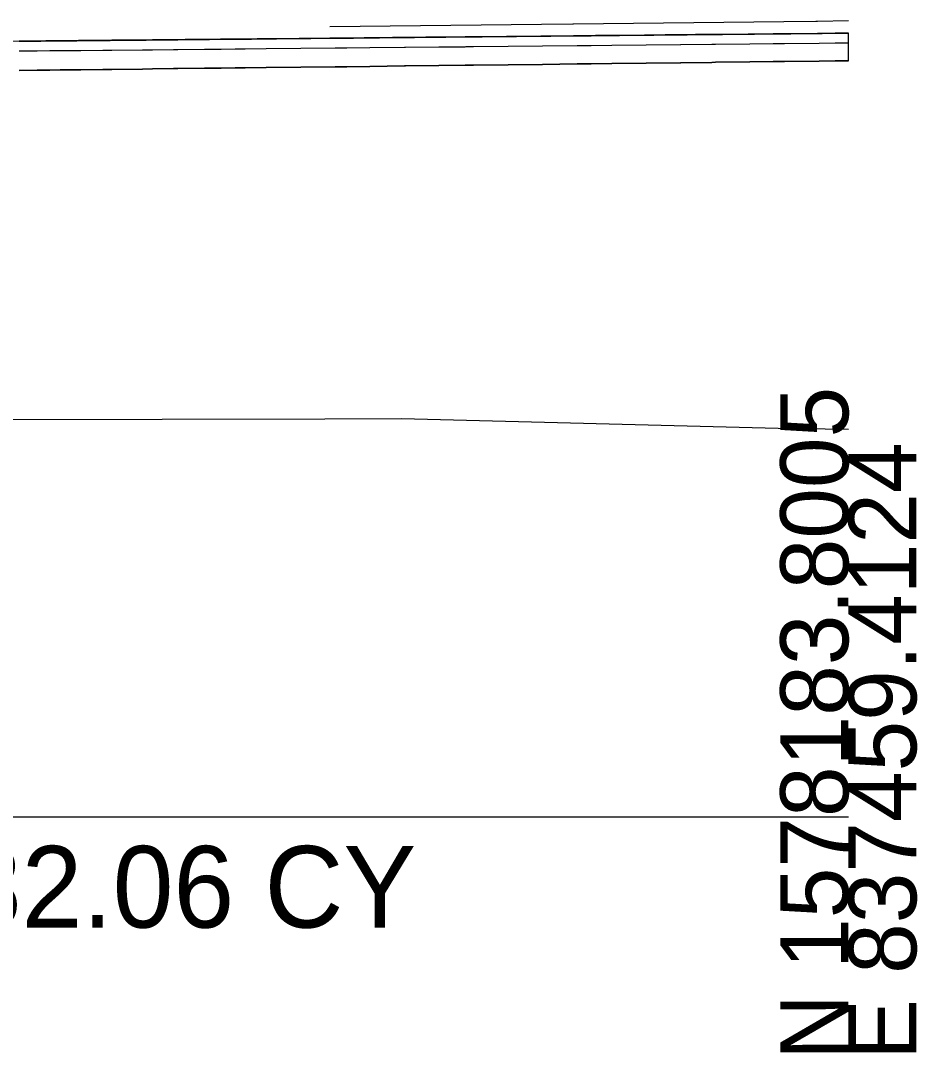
# Model space of a CAD drawing. Extents: x -26 to 303, y -16 to 6048.
# Drawn here: x 265.95 to 302.84, y 5990.31 to 6032.76 of the extents above; entities that cross this region are included whole.
import ezdxf

# ---------------------------------------------------------------- set-up
doc = ezdxf.new("R2010")
doc.units = 0
for name, color, linetype in [('CONST_LV3', 7, 'Continuous'), ('DTM_P_FINISHED_GRADE2', 7, 'Continuous'), ('DTM_X_GROUND', 7, 'Continuous'), ('XS_CELL', 7, 'Continuous'), ('XS_M_SHAPES_EARTHWORK', 7, 'Continuous'), ('XS_P_ASPHALT', 7, 'Continuous'), ('XS_P_SHOULDER', 7, 'Continuous'), ('XS_P_SUBGRADE_GRANULAR', 7, 'Continuous'), ('XS_SHEET_EW_TX_VOLUME', 7, 'Continuous')]:
    doc.layers.add(name, color=color, linetype=linetype)

msp = doc.modelspace()

# ---------------------------------------------------------------- linework, layer by layer
at = {"layer": 'CONST_LV3'}
for points in [[(278.666, 6032.514), (287.381, 6032.613), (288.666, 6032.627), (288.697, 6032.628), (297.343, 6032.728), (298.667, 6032.744), (298.728, 6032.744), (300, 6032.759)], [(278.666, 6032.514), (287.381, 6032.613), (288.666, 6032.627), (288.697, 6032.628), (297.343, 6032.728), (298.667, 6032.744), (298.728, 6032.744), (300, 6032.759)], [(300, 6032.247), (298.729, 6032.234), (297.181, 6032.218), (296.244, 6032.209), (294.294, 6032.189), (293.713, 6032.183), (292.532, 6032.171), (292.463, 6032.17), (292.173, 6032.167), (288.744, 6032.133), (288.719, 6032.133), (288.698, 6032.133), (286.047, 6032.106), (283.682, 6032.083), (282.621, 6032.073), (281.244, 6032.059), (280.081, 6032.048), (278.666, 6032.034), (278.122, 6032.029), (277.485, 6032.023), (275.68, 6032.005), (273.744, 6031.987), (273.698, 6031.986), (273.65, 6031.986), (273.22, 6031.982), (272.777, 6031.978), (270.627, 6031.957), (268.634, 6031.939), (266.2, 6031.916), (264.364, 6031.899)]]:
    msp.add_lwpolyline(points, dxfattribs=at)
at = {"layer": 'DTM_P_FINISHED_GRADE2'}
msp.add_lwpolyline([(265.884, 6031.913), (266.206, 6031.916), (266.629, 6031.92), (266.933, 6031.923), (267.154, 6031.925), (267.399, 6031.927), (267.571, 6031.929), (267.917, 6031.932), (268.425, 6031.937), (268.973, 6031.942), (269.323, 6031.945), (269.465, 6031.947), (269.695, 6031.949), (270.5, 6031.956), (270.965, 6031.961), (271.112, 6031.962), (271.376, 6031.964), (271.94, 6031.97), (272.235, 6031.973), (272.295, 6031.973), (272.412, 6031.974), (272.774, 6031.978), (273.505, 6031.985), (273.721, 6031.987), (274.168, 6031.991), (274.179, 6031.991), (274.202, 6031.991), (274.386, 6031.993), (274.775, 6031.997), (274.904, 6031.998), (275.181, 6032.001), (275.451, 6032.003), (276.045, 6032.009), (276.479, 6032.013), (277.468, 6032.023), (277.888, 6032.027), (278.89, 6032.036), (278.918, 6032.037), (278.972, 6032.037), (279.04, 6032.038), (279.096, 6032.038), (279.229, 6032.04), (279.368, 6032.041), (279.638, 6032.044), (280.312, 6032.05), (280.707, 6032.054), (281.734, 6032.064), (281.745, 6032.064), (281.775, 6032.064), (282.146, 6032.068), (283.156, 6032.078), (283.439, 6032.081), (284.235, 6032.088), (284.246, 6032.089), (284.324, 6032.089), (284.354, 6032.09), (284.578, 6032.092), (284.938, 6032.095), (286, 6032.106), (286.348, 6032.109), (287.422, 6032.12), (287.759, 6032.123), (288.844, 6032.134), (288.96, 6032.135), (289.345, 6032.139), (289.361, 6032.139), (289.414, 6032.14), (289.608, 6032.142), (290.266, 6032.148), (290.582, 6032.151), (291.688, 6032.163), (291.991, 6032.166), (293.098, 6032.177), (293.101, 6032.177), (293.109, 6032.177), (293.374, 6032.18), (294.38, 6032.19), (294.411, 6032.19), (294.531, 6032.191), (294.816, 6032.194), (295.953, 6032.206), (296.14, 6032.208), (296.914, 6032.216), (297.002, 6032.216), (297.374, 6032.22), (297.64, 6032.223), (298.796, 6032.235), (298.917, 6032.236), (299.459, 6032.242), (299.595, 6032.243), (300, 6032.247)], dxfattribs=at)
at = {"layer": 'DTM_X_GROUND'}
for points in [[(265.884, 6031.913), (266.308, 6031.917), (266.629, 6031.92), (266.78, 6031.921), (266.985, 6031.923), (267.084, 6031.924), (267.154, 6031.925), (267.327, 6031.927), (267.571, 6031.929), (267.849, 6031.931), (268.256, 6031.935), (268.323, 6031.936), (268.425, 6031.937), (268.973, 6031.942), (269.323, 6031.945), (269.448, 6031.946), (269.526, 6031.947), (269.631, 6031.948), (269.695, 6031.949), (270.105, 6031.953), (270.796, 6031.959), (270.904, 6031.96), (270.965, 6031.961), (271.112, 6031.962), (271.376, 6031.964), (271.828, 6031.969), (272.066, 6031.971), (272.178, 6031.972), (272.235, 6031.973), (272.295, 6031.973), (272.412, 6031.974), (272.719, 6031.977), (273.336, 6031.983), (273.392, 6031.984), (273.505, 6031.985), (273.721, 6031.987), (274.168, 6031.991), (274.179, 6031.991), (274.309, 6031.992), (274.333, 6031.993), (274.607, 6031.995), (274.661, 6031.996), (274.775, 6031.997), (274.904, 6031.998), (275.181, 6032.001), (275.399, 6032.003), (275.876, 6032.007), (275.892, 6032.007), (275.908, 6032.008), (275.929, 6032.008), (275.964, 6032.008), (275.999, 6032.008), (276.045, 6032.009), (276.458, 6032.013), (277.4, 6032.022), (277.42, 6032.022), (277.468, 6032.023), (277.868, 6032.026), (278.822, 6032.036), (278.842, 6032.036), (278.87, 6032.036), (278.924, 6032.037), (278.972, 6032.037), (279.04, 6032.038), (279.096, 6032.038), (279.229, 6032.04), (279.368, 6032.041), (279.619, 6032.043), (280.244, 6032.049), (280.264, 6032.05), (280.312, 6032.05), (280.689, 6032.054), (281.667, 6032.063), (281.685, 6032.063), (281.696, 6032.064), (281.745, 6032.064), (281.775, 6032.064), (282.128, 6032.068), (283.089, 6032.077), (283.107, 6032.077), (283.156, 6032.078), (283.439, 6032.081), (284.235, 6032.088), (284.246, 6032.089), (284.307, 6032.089), (284.336, 6032.089), (284.354, 6032.09), (284.528, 6032.091), (284.578, 6032.092), (284.921, 6032.095), (285.933, 6032.105), (285.95, 6032.105), (286, 6032.106), (286.332, 6032.109), (287.355, 6032.119), (287.371, 6032.119), (287.422, 6032.12), (287.743, 6032.123), (288.777, 6032.133), (288.792, 6032.134), (288.844, 6032.134), (288.96, 6032.135), (289.345, 6032.139), (289.361, 6032.139), (289.414, 6032.14), (289.593, 6032.142), (290.198, 6032.148), (290.214, 6032.148), (290.266, 6032.148), (290.567, 6032.151), (291.62, 6032.162), (291.635, 6032.162), (291.688, 6032.163), (291.979, 6032.165), (293.042, 6032.176), (293.054, 6032.176), (293.056, 6032.176), (293.101, 6032.177), (293.109, 6032.177), (293.374, 6032.18), (294.38, 6032.19), (294.397, 6032.19), (294.411, 6032.19), (294.477, 6032.191), (294.531, 6032.191), (294.803, 6032.194), (295.885, 6032.205), (295.898, 6032.205), (295.953, 6032.206), (296.14, 6032.208), (296.914, 6032.216), (296.989, 6032.216), (297.002, 6032.216), (297.319, 6032.22), (297.374, 6032.22), (297.628, 6032.223), (298.728, 6032.234), (298.74, 6032.234), (298.796, 6032.235), (298.917, 6032.236), (299.459, 6032.242), (299.583, 6032.243), (300, 6032.247)], [(221.804, 6016.289), (230.273, 6016.114), (237.507, 6016.127), (244.659, 6016.14), (251.731, 6016.152), (258.137, 6016.339), (264.993, 6016.353), (271.767, 6016.367), (278.46, 6016.381), (281.614, 6016.388), (297.107, 6015.991), (300, 6015.945)]]:
    msp.add_lwpolyline(points, dxfattribs=at)
at = {"layer": 'XS_CELL'}
msp.add_line((150, 6000), (300, 6000), dxfattribs=at)
at = {"layer": 'XS_M_SHAPES_EARTHWORK'}
msp.add_lwpolyline([(265.884, 6030.712), (266.629, 6030.721), (267.154, 6030.726), (267.571, 6030.731), (268.425, 6030.741), (269.323, 6030.751), (269.695, 6030.755), (270.965, 6030.769), (271.376, 6030.774), (272.235, 6030.784), (272.412, 6030.786), (273.505, 6030.798), (274.168, 6030.806), (274.202, 6030.806), (274.775, 6030.813), (275.181, 6030.817), (276.045, 6030.827), (277.468, 6030.844), (278.89, 6030.86), (278.985, 6030.861), (279.172, 6030.863), (279.368, 6030.865), (280.312, 6030.876), (281.734, 6030.893), (281.775, 6030.893), (283.156, 6030.909), (284.235, 6030.922), (284.275, 6030.923), (284.578, 6030.926), (286, 6030.943), (287.422, 6030.96), (288.844, 6030.976), (289.345, 6030.982), (289.414, 6030.983), (290.266, 6030.993), (291.688, 6031.01), (293.098, 6031.027), (293.109, 6031.027), (294.38, 6031.043), (294.531, 6031.044), (295.953, 6031.062), (296.914, 6031.073), (297.374, 6031.079), (298.796, 6031.096), (299.459, 6031.104), (300, 6031.111), (300, 6032.247), (299.583, 6032.243), (299.459, 6032.242), (298.917, 6032.236), (298.796, 6032.235), (298.74, 6032.234), (298.728, 6032.234), (297.628, 6032.223), (297.374, 6032.22), (297.319, 6032.22), (297.002, 6032.216), (296.989, 6032.216), (296.914, 6032.216), (296.14, 6032.208), (295.953, 6032.206), (295.898, 6032.205), (295.885, 6032.205), (294.803, 6032.194), (294.531, 6032.191), (294.477, 6032.191), (294.411, 6032.19), (294.397, 6032.19), (294.38, 6032.19), (293.374, 6032.18), (293.109, 6032.177), (293.101, 6032.177), (293.056, 6032.176), (293.054, 6032.176), (293.042, 6032.176), (291.979, 6032.165), (291.688, 6032.163), (291.635, 6032.162), (291.62, 6032.162), (290.567, 6032.151), (290.266, 6032.148), (290.214, 6032.148), (290.198, 6032.148), (289.593, 6032.142), (289.414, 6032.14), (289.361, 6032.139), (289.345, 6032.139), (288.96, 6032.135), (288.844, 6032.134), (288.792, 6032.134), (288.777, 6032.133), (287.743, 6032.123), (287.422, 6032.12), (287.371, 6032.119), (287.355, 6032.119), (286.332, 6032.109), (286, 6032.106), (285.95, 6032.105), (285.933, 6032.105), (284.921, 6032.095), (284.578, 6032.092), (284.528, 6032.091), (284.354, 6032.09), (284.336, 6032.089), (284.307, 6032.089), (284.246, 6032.089), (284.235, 6032.088), (283.439, 6032.081), (283.156, 6032.078), (283.107, 6032.077), (283.089, 6032.077), (282.128, 6032.068), (281.775, 6032.064), (281.745, 6032.064), (281.696, 6032.064), (281.685, 6032.063), (281.667, 6032.063), (280.689, 6032.054), (280.312, 6032.05), (280.264, 6032.05), (280.244, 6032.049), (279.619, 6032.043), (279.368, 6032.041), (279.229, 6032.04), (279.096, 6032.038), (279.04, 6032.038), (278.972, 6032.037), (278.924, 6032.037), (278.87, 6032.036), (278.842, 6032.036), (278.822, 6032.036), (277.868, 6032.026), (277.468, 6032.023), (277.42, 6032.022), (277.4, 6032.022), (276.458, 6032.013), (276.045, 6032.009), (275.999, 6032.008), (275.964, 6032.008), (275.929, 6032.008), (275.908, 6032.008), (275.892, 6032.007), (275.876, 6032.007), (275.399, 6032.003), (275.181, 6032.001), (274.904, 6031.998), (274.775, 6031.997), (274.661, 6031.996), (274.607, 6031.995), (274.333, 6031.993), (274.309, 6031.992), (274.179, 6031.991), (274.168, 6031.991), (273.721, 6031.987), (273.505, 6031.985), (273.392, 6031.984), (273.336, 6031.983), (272.719, 6031.977), (272.412, 6031.974), (272.295, 6031.973), (272.235, 6031.973), (272.178, 6031.972), (272.066, 6031.971), (271.828, 6031.969), (271.376, 6031.964), (271.112, 6031.962), (270.965, 6031.961), (270.904, 6031.96), (270.796, 6031.959), (270.105, 6031.953), (269.695, 6031.949), (269.631, 6031.948), (269.526, 6031.947), (269.448, 6031.946), (269.323, 6031.945), (268.973, 6031.942), (268.425, 6031.937), (268.323, 6031.936), (268.256, 6031.935), (267.849, 6031.931), (267.571, 6031.929), (267.327, 6031.927), (267.154, 6031.925), (267.084, 6031.924), (266.985, 6031.923), (266.78, 6031.921), (266.629, 6031.92), (266.308, 6031.917), (265.884, 6031.913)], dxfattribs=at)
at = {"layer": 'XS_P_ASPHALT'}
for points in [[(300, 6031.847), (300, 6032.247), (300, 6032.247), (299.459, 6032.242), (299.459, 6032.242), (298.796, 6032.235), (298.796, 6032.235), (297.374, 6032.22), (297.374, 6032.22), (296.914, 6032.216), (296.914, 6032.216), (295.953, 6032.206), (295.953, 6032.206), (294.531, 6032.191), (294.531, 6032.191), (294.38, 6032.19), (294.38, 6032.19), (293.109, 6032.177), (293.109, 6032.177), (293.098, 6032.177), (293.098, 6032.177), (291.688, 6032.163), (291.688, 6032.163), (290.266, 6032.148), (290.266, 6032.148), (289.414, 6032.14), (289.414, 6032.14), (289.345, 6032.139), (289.345, 6032.139), (288.844, 6032.134), (288.844, 6032.134), (287.422, 6032.12), (287.422, 6032.12), (286, 6032.106), (286, 6032.106), (284.578, 6032.092), (284.578, 6032.092), (284.275, 6032.089), (284.275, 6032.089), (284.235, 6032.088), (284.235, 6032.088), (283.156, 6032.078), (283.156, 6032.078), (281.775, 6032.064), (281.775, 6032.064), (281.734, 6032.064), (281.734, 6032.064), (280.312, 6032.05), (280.312, 6032.05), (279.368, 6032.041), (279.368, 6032.041), (279.172, 6032.039), (279.172, 6032.039), (278.985, 6032.037), (278.985, 6032.037), (278.89, 6032.036), (278.89, 6032.036), (277.468, 6032.023), (277.468, 6032.023), (276.045, 6032.009), (276.045, 6032.009), (275.181, 6032.001), (275.181, 6032.001), (274.775, 6031.997), (274.775, 6031.997), (274.202, 6031.991), (274.202, 6031.991), (274.168, 6031.991), (274.168, 6031.991), (273.505, 6031.985), (273.505, 6031.985), (272.412, 6031.974), (272.412, 6031.974), (272.235, 6031.973), (272.235, 6031.973), (271.376, 6031.964), (271.376, 6031.964), (270.965, 6031.961), (270.965, 6031.961), (269.695, 6031.949), (269.695, 6031.949), (269.323, 6031.945), (269.323, 6031.945), (268.425, 6031.937), (268.425, 6031.937), (267.571, 6031.929), (267.571, 6031.929), (267.154, 6031.925), (267.154, 6031.925), (266.629, 6031.92), (266.629, 6031.92), (265.884, 6031.913)], [(265.884, 6031.513), (266.629, 6031.52), (266.629, 6031.52), (267.154, 6031.525), (267.154, 6031.525), (267.571, 6031.529), (267.571, 6031.529), (268.425, 6031.537), (268.425, 6031.537), (269.323, 6031.545), (269.323, 6031.545), (269.695, 6031.549), (269.695, 6031.549), (270.965, 6031.561), (270.965, 6031.561), (271.376, 6031.564), (271.376, 6031.564), (272.235, 6031.573), (272.235, 6031.573), (272.412, 6031.574), (272.412, 6031.574), (273.505, 6031.585), (273.505, 6031.585), (274.168, 6031.591), (274.168, 6031.591), (274.202, 6031.591), (274.202, 6031.591), (274.775, 6031.597), (274.775, 6031.597), (275.181, 6031.601), (275.181, 6031.601), (276.045, 6031.609), (276.045, 6031.609), (277.468, 6031.623), (277.468, 6031.623), (278.89, 6031.636), (278.89, 6031.636), (278.985, 6031.637), (278.985, 6031.637), (279.172, 6031.639), (279.172, 6031.639), (279.368, 6031.641), (279.368, 6031.641), (280.312, 6031.65), (280.312, 6031.65), (281.734, 6031.664), (281.734, 6031.664), (281.775, 6031.664), (281.775, 6031.664), (283.156, 6031.678), (283.156, 6031.678), (284.235, 6031.688), (284.235, 6031.688), (284.275, 6031.689), (284.275, 6031.689), (284.578, 6031.692), (284.578, 6031.692), (286, 6031.706), (286, 6031.706), (287.422, 6031.72), (287.422, 6031.72), (288.844, 6031.734), (288.844, 6031.734), (289.345, 6031.739), (289.345, 6031.739), (289.414, 6031.74), (289.414, 6031.74), (290.266, 6031.748), (290.266, 6031.748), (291.688, 6031.763), (291.688, 6031.763), (293.098, 6031.777), (293.098, 6031.777), (293.109, 6031.777), (293.109, 6031.777), (294.38, 6031.79), (294.38, 6031.79), (294.531, 6031.791), (294.531, 6031.791), (295.953, 6031.806), (295.953, 6031.806), (296.914, 6031.816), (296.914, 6031.816), (297.374, 6031.82), (297.374, 6031.82), (298.796, 6031.835), (298.796, 6031.835), (299.459, 6031.842), (299.459, 6031.842), (300, 6031.847)]]:
    msp.add_lwpolyline(points, dxfattribs=at)
at = {"layer": 'XS_P_SHOULDER'}
msp.add_lwpolyline([(300, 6032.247), (299.459, 6032.242), (298.796, 6032.235), (297.374, 6032.22), (296.914, 6032.216), (295.953, 6032.206), (294.531, 6032.191), (294.38, 6032.19), (293.109, 6032.177), (293.098, 6032.177), (291.688, 6032.163), (290.266, 6032.148), (289.414, 6032.14), (289.345, 6032.139), (288.844, 6032.134), (287.422, 6032.12), (286, 6032.106), (284.578, 6032.092), (284.275, 6032.089), (284.235, 6032.088), (283.156, 6032.078), (281.775, 6032.064), (281.734, 6032.064), (280.312, 6032.05), (279.368, 6032.041), (279.172, 6032.039), (278.985, 6032.037), (278.89, 6032.036), (277.468, 6032.023), (276.045, 6032.009), (275.181, 6032.001), (274.775, 6031.997), (274.202, 6031.991), (274.168, 6031.991), (273.505, 6031.985), (272.412, 6031.974), (272.235, 6031.973), (271.376, 6031.964), (270.965, 6031.961), (269.695, 6031.949), (269.323, 6031.945), (268.425, 6031.937), (267.571, 6031.929), (267.154, 6031.925), (266.629, 6031.92), (265.884, 6031.913)], dxfattribs=at)
at = {"layer": 'XS_P_SUBGRADE_GRANULAR'}
msp.add_lwpolyline([(300, 6031.111), (299.459, 6031.104), (298.796, 6031.096), (297.374, 6031.079), (296.914, 6031.073), (295.953, 6031.062), (294.531, 6031.044), (294.38, 6031.043), (293.109, 6031.027), (293.098, 6031.027), (291.688, 6031.01), (290.266, 6030.993), (289.414, 6030.983), (289.345, 6030.982), (288.844, 6030.976), (287.422, 6030.96), (286, 6030.943), (284.578, 6030.926), (284.275, 6030.923), (284.235, 6030.922), (283.156, 6030.909), (281.775, 6030.893), (281.734, 6030.893), (280.312, 6030.876), (279.368, 6030.865), (279.172, 6030.863), (278.985, 6030.861), (278.89, 6030.86), (277.468, 6030.844), (276.045, 6030.827), (275.181, 6030.817), (274.775, 6030.813), (274.202, 6030.806), (274.168, 6030.806), (273.505, 6030.798), (272.412, 6030.786), (272.235, 6030.784), (271.376, 6030.774), (270.965, 6030.769), (269.695, 6030.755), (269.323, 6030.751), (268.425, 6030.741), (267.571, 6030.731), (267.154, 6030.726), (266.629, 6030.721), (265.884, 6030.712)], dxfattribs=at)

# ---------------------------------------------------------------- texts
at = {"layer": 'XS_CELL'}
for s, p in [('N 1578183.8005', (300, 5990)), ('E 837459.4124', (302.8, 5990))]:
    msp.add_text(s, height=2.8, rotation=90, dxfattribs=at).set_placement(p)
at = {"layer": 'XS_SHEET_EW_TX_VOLUME'}
msp.add_text('CV: 282.06 CY', height=3.36, dxfattribs=at).set_placement((252.252, 5995.44))

doc.saveas('drawing.dxf')
